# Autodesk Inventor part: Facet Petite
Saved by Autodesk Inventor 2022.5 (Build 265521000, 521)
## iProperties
Created: 2024-07
Part Number: Facet Petite
Material: Generic
Document SubType Name: Modeling
Designer: AdminForWorker
Density: 1 g/cm^3
Appearance: Default
Title: Facet Petite
Author: AdminForWorker
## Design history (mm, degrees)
feature "Body1"
body "Solid1"
